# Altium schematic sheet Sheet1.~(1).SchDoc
size A4
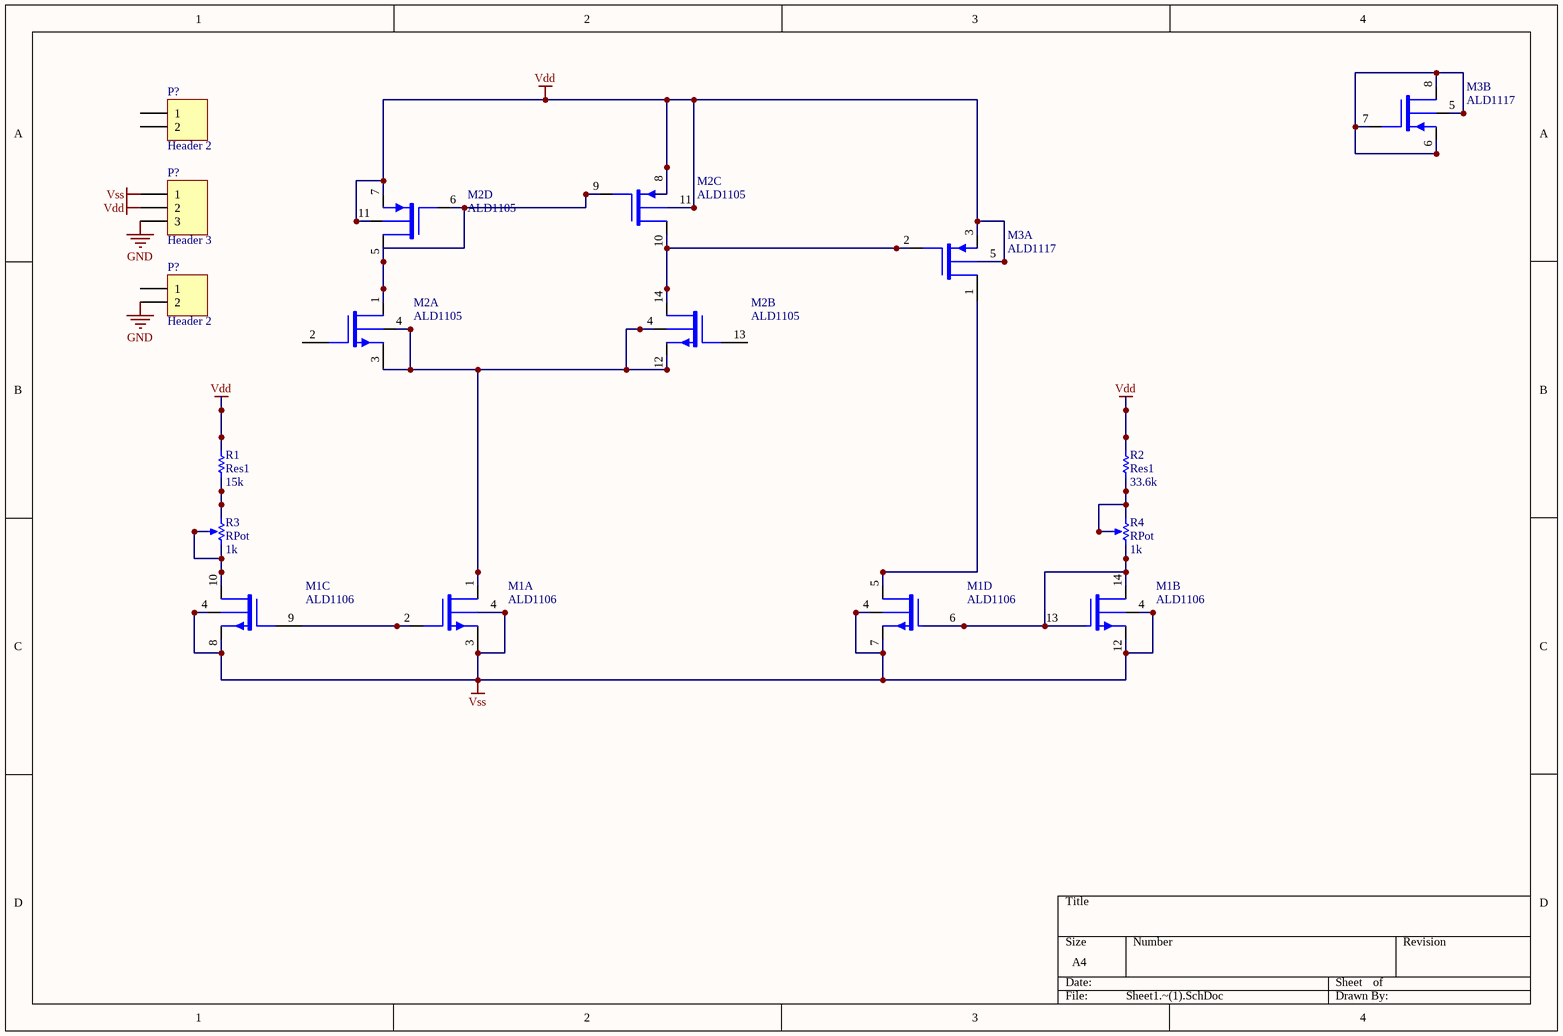
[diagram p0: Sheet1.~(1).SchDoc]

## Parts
(Parts that share a designator on the sheet are numbered #1, #2 ... from top to bottom, then left to right.)
M1  ALD1106  [DIP-14]  (parts A,B,C,D of 4)
M2  ALD1105  [DIP-14]  (parts A,B,C,D of 4)
M3  ALD1117  [DIP-8]  (parts A,B of 2)
P?#1  Header 2  [HDR1X2]
P?#2  Header 3  [HDR1X3]
P?#3  Header 2  [HDR1X2]
R1  Res1  value 15k  [AXIAL-0.3]
R2  Res1  value 33.6k  [AXIAL-0.3]
R3  RPot  value 1k  [VR5]
R4  RPot  value 1k  [VR5]

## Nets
GND: P?#2.3 P?#3.2
Vdd: M2.7(SP1) M2.8(SP2) M2.11(V+) M3.3(SP1) M3.5(V+) P?#2.2 R1.2 R2.2
Vss: M1.3(SN1) M1.4(V-) M1.7(SN4) M1.8(SN3) M1.12(SN2) P?#2.1
NetM1_1: M1.1(DN1) M2.3(SN1) M2.4(V-) M2.12(SN2)
NetM1_2: M1.2(GN1) M1.9(GN3)
NetM1_5: M1.5(DN4) M3.1(DP1)
NetM1_6: M1.6(GN4) M1.13(GN2) M1.14(DN2) R4.3(BOT)
NetM1_10: M1.10(DN3) R3.2(TAP) R3.3(BOT)
NetM2_1: M2.1(DN1) M2.5(DP1) M2.6(GP1) M2.9(GP2)
NetM2_10: M2.10(DP2) M2.14(DN2) M3.2(GP1)
NetM3_5: M3.5(V+) M3.6(SP2) M3.7(GP2) M3.8(DP2)
NetR1_1: R1.1 R3.1(TOP)
NetR2_1: R2.1 R4.1(TOP) R4.2(TAP)

Not connected (* = marked no-connect by the designer): M2 2(GN1) 13(GN2); P?#1 1 2; P?#3 1

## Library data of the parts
M1 = ALD1106: Quad N-channel matched MOSFET array
M2 = ALD1105: Dual P-channel and dual N-channel matched MOSFET array
M3 = ALD1117: Dual P-channel matched MOSFET array
P?#1 P?#3 = Header 2: Header, 2-Pin
P?#2 = Header 3: Header, 3-Pin
R1 R2 = Res1: Resistor
R3 R4 = RPot: Potentiometer; Sim Note: Enter the Resistance value and the set point into parameter fields.; Set Position: 0.5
